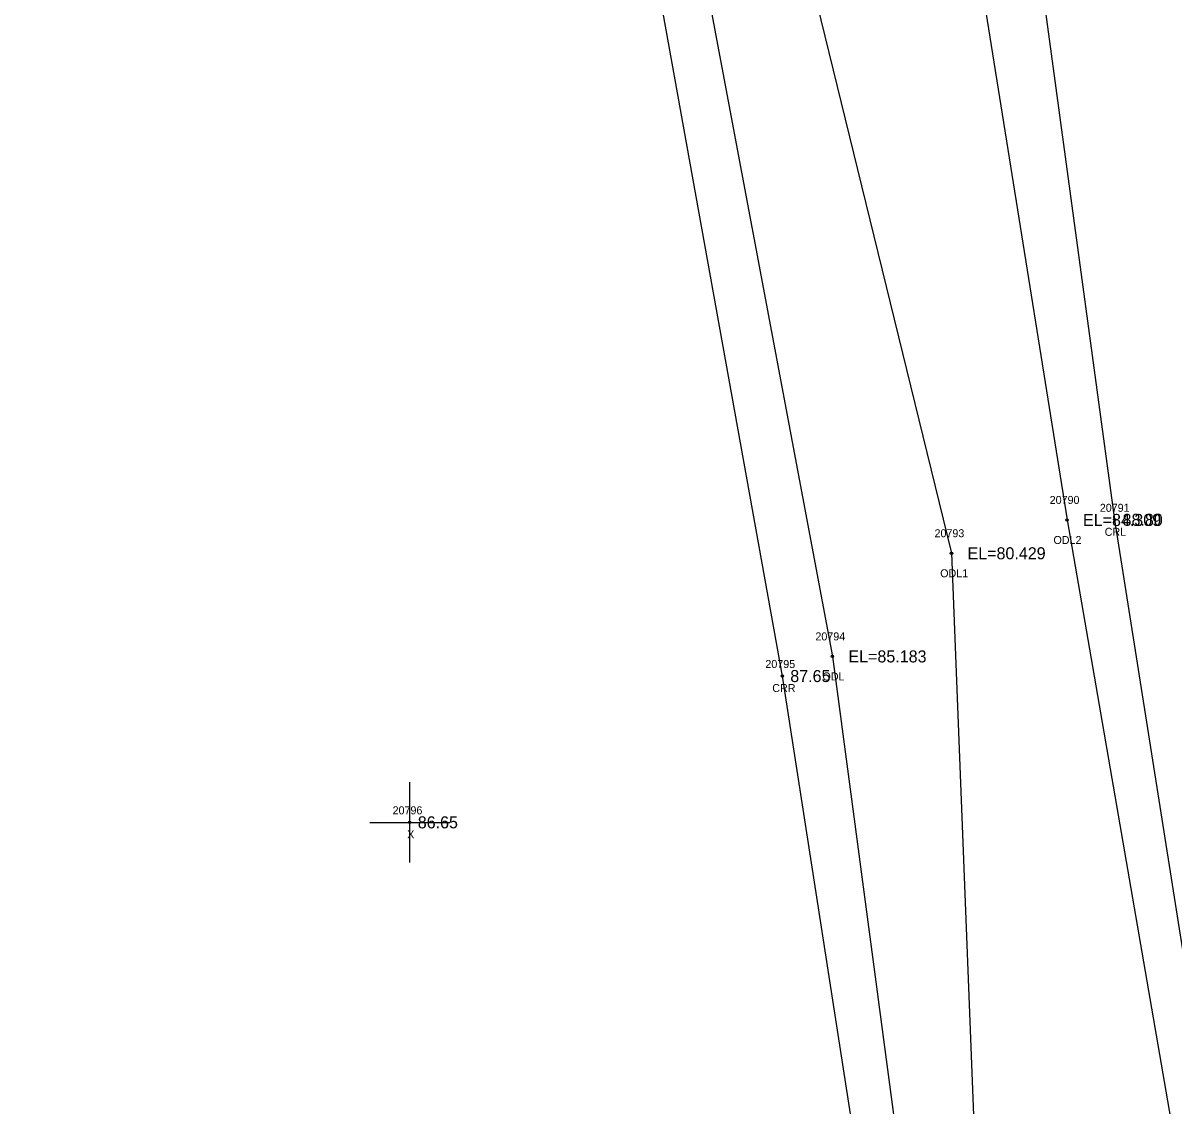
# Model space of a CAD drawing. Extents: x 2530197 to 2532051, y 935230 to 936631.
# Drawn here: x 2531078.9 to 2531222.7, y 935599.2 to 935734.5 of the extents above; entities that cross this region are included whole.
import ezdxf

# ---------------------------------------------------------------- set-up
doc = ezdxf.new("R2010")
doc.units = 0
for name, color, linetype in [('RD_EX_H2O', 7, 'Continuous'), ('RD_EX_H2O_txCode', 7, 'Continuous'), ('RD_EX_Misc', 7, 'Continuous'), ('RD_EX_Misc_txCode', 7, 'Continuous'), ('RD_EX_TX_H2O_ELEV', 7, 'Continuous'), ('RD_EX_TX_Misc_ELEV', 7, 'Continuous'), ('RD_SMD_Locator', 7, 'Continuous')]:
    doc.layers.add(name, color=color, linetype=linetype)

msp = doc.modelspace()

# ---------------------------------------------------------------- linework, layer by layer
at = {"layer": 'RD_EX_H2O'}
for points in [[(2531169.61, 936003.09), (2531168.21, 936006.21), (2531167.04, 936004.54), (2531167.21, 936003.45), (2531176, 935975.44), (2531176.84, 935974.76), (2531177.07, 935973.85), (2531179, 935967.11), (2531180.39, 935948.02), (2531175.92, 935941.33), (2531173.5, 935933.2), (2531181.71, 935892.9), (2531201.16, 935775.97), (2531215.24, 935672.42), (2531231.54, 935569.22), (2531229.65, 935447.9)], [(2531151.41, 935999.3), (2531160.42, 935966.87), (2531174.33, 935892.02), (2531192.74, 935775.85), (2531209.3, 935672.4), (2531227.01, 935569.99), (2531223.19, 935447.63)], [(2531123.96, 935982.91), (2531138.41, 935953.66), (2531150.01, 935894.11), (2531170.89, 935766.15), (2531194.87, 935668.24), (2531198.82, 935567.24), (2531215.76, 935447.86)], [(2531095.07, 935962.75), (2531122.05, 935944.01), (2531139.42, 935896.32), (2531161, 935756.43), (2531179.99, 935655.36), (2531191.29, 935570.65), (2531207.98, 935448.59)], [(2531078.88, 935952.28), (2531078.96, 935951.18), (2531094.18, 935926.97), (2531103.29, 935929.49), (2531106.67, 935929.67), (2531109.75, 935927.85), (2531109.94, 935928.67), (2531111.53, 935928.19), (2531109.98, 935924.15), (2531114.47, 935921.71), (2531121.2, 935920.45), (2531134.65, 935891.6), (2531155.43, 935754.46), (2531173.73, 935652.91), (2531186.19, 935572.51), (2531201.43, 935446.7)]]:
    msp.add_lwpolyline(points, dxfattribs=at)
at = {"layer": 'RD_EX_Misc'}
for p, q in [((2531127.19, 935629.64), (2531127.19, 935639.64)), ((2531122.19, 935634.64), (2531132.19, 935634.64))]:
    msp.add_line(p, q, dxfattribs=at)
at = {"layer": 'RD_SMD_Locator'}
for centre in [(2531209.3, 935672.4), (2531215.24, 935672.42), (2531194.87, 935668.24), (2531179.99, 935655.36), (2531173.73, 935652.91), (2531127.19, 935634.64)]:
    msp.add_circle(centre, 0.15, dxfattribs=at)

# ---------------------------------------------------------------- texts
at = {"layer": 'RD_EX_H2O_txCode'}
for s, p in [('20790', (2531207.14, 935674.4)), ('20791', (2531213.4, 935673.42)), ('20793', (2531192.75, 935670.24)), ('CRL', (2531214.01, 935670.42)), ('ODL2', (2531207.61, 935669.4)), ('ODL1', (2531193.46, 935665.24)), ('20794', (2531177.87, 935657.36)), ('20795', (2531171.62, 935653.91)), ('ODL', (2531178.75, 935652.36)), ('CRR', (2531172.48, 935650.91))]:
    msp.add_text(s, height=1, dxfattribs=at).set_placement(p)
at = {"layer": 'RD_EX_Misc_txCode'}
for s, p in [('20796', (2531125.05, 935635.64)), ('X', (2531126.87, 935632.64))]:
    msp.add_text(s, height=1, dxfattribs=at).set_placement(p)
at = {"layer": 'RD_EX_TX_H2O_ELEV'}
for s, p in [('EL=84.309', (2531211.3, 935671.65)), ('88.80', (2531216.24, 935671.67)), ('EL=80.429', (2531196.87, 935667.49)), ('EL=85.183', (2531181.99, 935654.61)), ('87.65', (2531174.73, 935652.16))]:
    msp.add_text(s, height=1.5, dxfattribs=at).set_placement(p)
at = {"layer": 'RD_EX_TX_Misc_ELEV'}
msp.add_text('86.65', height=1.5, dxfattribs=at).set_placement((2531128.19, 935633.89))

doc.saveas('drawing.dxf')
